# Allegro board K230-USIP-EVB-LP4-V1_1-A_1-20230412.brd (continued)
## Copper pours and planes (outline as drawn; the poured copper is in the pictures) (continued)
GND on TOP: 64.64,40.01 64.52,40.13 64.52,42.8 64.01,43.31 60.96,43.31 60.83,43.43 60.83,47.75 60.96,47.88 63.37,47.88 63.5,48.01 63.5,50.55 63.63,50.67 66.93,50.67 67.06,50.55 67.06,43.69 67.31,43.43 75.18,43.43 75.31,43.31 75.31,40.13 75.18,40.01
GND on TOP: 59.31,85.47 59.31,88.39 59.44,88.52 62.61,88.52 62.87,88.27 62.87,85.47 62.74,85.34 59.44,85.34
GND on TOP: 67.18,9.91 67.31,9.78 67.31,2.03 67.18,1.91 45.47,1.91 45.34,2.03 45.34,9.78 45.47,9.91
GND on TOP: 23.37,64.9 23.24,64.77 20.45,64.77 20.32,64.9 20.32,66.55 20.45,66.67 23.24,66.67 23.37,66.55 ; 1 cut-out
GND on TOP: 31.62,19.68 31.5,19.81 31.5,21.59 31.62,21.72 34.67,21.72 34.8,21.59 34.8,19.81 34.67,19.68
GND on BOTTOM: 54.36,119.51 54.36,129.54 56.64,131.83 60.83,131.83 60.96,131.7 60.96,128.27 58.8,126.11 58.8,124.33 60.96,122.17 60.96,118.24 60.83,118.11 55.75,118.11
GND on BOTTOM: 1.27,127.51 7.49,127.51 14.35,134.37 38.1,134.37 38.61,133.86 38.61,122.05 37.85,121.28 28.7,121.28 27.43,120.02 27.43,103.38 27.18,103.12 1.27,103.12 1.02,103.38 1.02,127.25
GND on BOTTOM: 21.34,49.53 21.21,49.66 21.21,50.67 21.34,50.8 23.11,50.8 23.24,50.67 23.24,49.66 23.11,49.53
GND on BOTTOM: 20.07,47.12 20.07,46.1 19.94,45.97 18.92,45.97 18.8,46.1 18.8,47.12 18.92,47.24 19.94,47.24
GND on BOTTOM: 35.81,50.67 35.94,50.55 35.94,49.66 35.81,49.53 34.04,49.53 33.91,49.66 33.91,50.55 34.04,50.67
GND on BOTTOM: 41.27,116.97 41.4,116.84 41.4,116.33 41.27,116.2 40.64,116.2 40.51,116.08 40.51,115.57 40.39,115.44 36.45,115.44 36.32,115.57 36.32,116.84 36.45,116.97
GND on BOTTOM: 21.34,45.59 22.86,45.59 22.99,45.47 22.99,44.2 22.86,44.07 21.34,44.07 21.21,44.2 21.21,45.47
GND on BOTTOM: 31.62,47.24 32.64,47.24 32.77,47.12 32.77,46.1 32.64,45.97 31.62,45.97 31.5,46.1 31.5,47.12
GND on BOTTOM: 73.66,89.28 75.69,89.28 75.82,89.15 75.82,85.98 75.69,85.85 73.66,85.85 73.53,85.98 73.53,89.15
GND on BOTTOM: 2,0.64 1.03,1.03 0.64,2 0.64,14.99 0.89,15.24 66.55,15.24 66.93,14.86 66.93,1.14 66.42,0.64
GND on BOTTOM: 33.78,44.07 33.78,45.59 33.91,45.72 35.56,45.72 35.69,45.59 35.69,44.07 35.56,43.94 33.91,43.94
GND on BOTTOM: 57.54,111.53 57.67,111.65 63.76,111.65 63.89,111.53 63.89,105.43 63.76,105.3 57.67,105.3 57.54,105.43
GND on GND02, GND05, GND07: 2,0.64 1.03,1.03 0.64,2 0.64,138 1.03,138.96 2,139.36 78.07,139.36 79.03,138.96 79.43,138 79.43,2 79.03,1.03 78.07,0.64
GND on ART03: 2,0.64 1.03,1.03 0.64,2 0.64,138 1.03,138.96 2,139.36 78.07,139.36 79.03,138.96 79.43,138 79.43,2 79.03,1.03 78.07,0.64 ; 1 cut-out
GND on POWER04: 2,0.64 1.03,1.03 0.64,2 0.64,53.47 1.27,54.1 2.03,54.1 3.05,53.09 3.05,15.24 3.56,14.73 69.85,14.73 70.36,15.24 70.36,41.66 75.69,46.99 75.69,116.2 57.53,134.37 5.59,134.37 4.06,132.84 4.06,115.99 2.01,114 4.06,112.01 4.06,78.3 3.53,77.49 4.04,76.65 4.04,75.75 3.53,74.84 4.2,74.05 4.19,74.04 4.19,72.14 3.81,71.75 1.14,71.75 0.64,72.26 0.64,78.65 0.69,78.74 0.79,78.74 1.45,79.11 0.79,79.48 0.69,79.48 0.64,79.56 0.64,138 1.03,138.96 2,139.36 78.07,139.36 79.03,138.96 79.43,138 79.43,2 79.03,1.03 78.07,0.64
GND on ART06: 1.02,89.41 0.64,89.79 0.64,138 1.03,138.96 2,139.36 26.04,139.36 26.29,139.11 26.29,136.78 5.59,116.08 5.59,89.79 5.21,89.41
GND on ART06: 47.75,34.8 65.28,34.8 65.53,34.54 65.53,20.7 63.25,18.41 47.5,18.41 47.37,18.54 47.37,34.42
GND on ART06: 74.68,123.44 69.72,118.49 64.77,118.49 62.99,116.71 56.01,116.71 51.56,112.27 50.55,112.27 50.42,112.39 50.42,114.94 54.61,119.13 54.61,132.72 56.01,134.11 71.37,134.11 74.68,130.81
GND on ART06: 10.16,41.27 33.53,41.27 33.78,41.02 33.78,14.86 33.53,14.61 10.29,14.61 9.91,14.99 9.91,41.02
GND on ART06: 2,0.64 1.03,1.03 0.64,2 0.64,9.4 1.02,9.78 30.48,9.78 30.73,9.53 30.73,1.14 30.23,0.64
GND on ART06: 45.09,1.02 45.09,10.29 50.29,15.49 66.74,15.49 74.36,23.11 74.36,53.66 72.01,56.01 72.01,81.03 75.56,84.58 75.56,108.46 74.17,109.86 74.17,119.57 75.5,120.9 75.5,131.38 71.75,135.13 59.56,135.13 59.44,135.25 59.44,139.24 59.56,139.36 78.07,139.36 79.03,138.96 79.43,138 79.43,2 79.03,1.03 78.07,0.64 45.47,0.64
VBUS on TOP: 73.03,11.18 69.47,11.18 69.22,11.43 69.22,16.26 69.72,16.76 73.15,16.76 73.28,16.64 73.28,16.26 73.15,16.13 71.25,16.13 71.12,16 71.12,11.94 71.25,11.81 73.03,11.81 73.15,11.68 73.15,11.3
VBUS_IN on TOP: 67.94,16.26 67.94,11.81 67.69,11.56 47.62,11.56 47.5,11.68 47.5,19.05 47.62,19.18 54.99,19.18 55.12,19.05 55.12,18.29 55.24,18.16 63.25,18.16 65.79,20.7 65.79,32.77 65.91,32.89 71.63,32.89 71.75,33.02 71.75,34.16 71.88,34.29 73.41,34.29 73.53,34.16 73.53,30.73 72.64,29.84 70.87,29.84 70.36,29.34 70.36,18.67
VDD_0V8 on TOP: 60.2,39.88 60.33,40.01 60.33,58.04 60.2,58.17 57.28,58.17 57.15,58.04 57.15,40.01 57.28,39.88
VDD_1V1 on TOP: 49.4,25.91 49.53,25.78 49.53,22.73 49.4,22.61 42.04,22.61 41.91,22.73 41.91,25.78 42.04,25.91
VDD_1V8 on TOP: 49.66,38.86 49.53,38.73 46.86,38.73 46.74,38.86 46.74,56.39 46.86,56.52 47.5,56.52 49.66,54.36
VDD_1V8 on BOTTOM: 25.4,80.01 25.53,79.88 25.53,76.71 25.4,76.58 24.38,76.58 24.26,76.71 24.26,77.34 24.13,77.47 22.35,77.47 22.23,77.6 22.23,79.88 22.35,80.01
VDD_1V8 on BOTTOM: 30.35,82.42 29.97,82.8 29.59,82.8 29.46,82.93 29.46,85.34 28.83,85.98 28.83,86.49 28.96,86.61 30.23,86.61 30.35,86.49 30.35,83.19 30.73,82.8 30.73,82.55 30.61,82.42
VDD_1V8 on BOTTOM: 36.2,114.68 37.47,114.68 37.59,114.55 37.59,113.03 36.96,112.39 36.96,111.89 36.83,111.76 36.2,111.76 36.07,111.89 36.07,114.55
VDD_1V8 on POWER04: 3.56,16.13 3.56,53.34 1.02,55.88 1.02,70.1 2.03,71.12 5.08,71.12 5.21,71.25 5.21,132.72 5.84,133.35 57.02,133.35 74.93,115.44 74.93,48.9 69.47,43.43 69.47,16 69.25,15.78 3.91,15.78 ; 1 cut-out
VDD_1V8 on ART06: 24.96,77.41 24.96,79.57 28.45,83.06 30.86,83.06 30.99,82.93 30.99,80.01 31.11,79.88 32.77,79.88 32.89,79.76 32.89,77.72 32.77,77.6 26.04,77.6 25.65,77.22 25.15,77.22
VDD_3V3 on TOP: 69.47,110.74 72.52,110.74 72.64,110.62 72.64,109.98 72.52,109.86 69.47,109.86 69.34,109.98 69.34,110.62
VDD_3V3 on TOP: 41.53,34.67 45.59,34.67 45.72,34.54 45.72,33.27 45.59,33.15 41.53,33.15 41.4,33.27 41.4,34.54
VDD_3V3 on TOP: 34.8,14.99 34.67,14.86 31.62,14.86 31.5,14.99 31.5,19.18 31.62,19.3 34.67,19.3 34.8,19.18
VDD_3V3 on TOP: 50.8,129.16 50.93,129.03 50.93,128.4 50.8,128.27 46.61,128.27 46.48,128.4 46.48,129.03 46.61,129.16
VDD_3V3 on TOP: 63.88,22.1 64.01,21.97 64.01,19.81 62.87,18.67 60.07,18.67 59.94,18.8 59.94,21.97 60.07,22.1
VDD_3V3 on TOP: 21.59,26.29 20.95,25.65 20.95,21.59 20.83,21.46 11.68,21.46 11.56,21.59 11.56,30.35 11.68,30.48 21.46,30.48 21.59,30.35
VDD_3V3 on BOTTOM: 70.87,89.28 72.9,89.28 73.03,89.15 73.03,85.98 72.9,85.85 70.87,85.85 70.74,85.98 70.74,89.15
VDD_3V3 on BOTTOM: 34.16,80.9 34.29,80.77 35.94,80.77 36.07,80.64 36.07,80.14 35.94,80.01 33.53,80.01 33.15,80.39 33.15,80.77 33.27,80.9
VDD_3V3 on BOTTOM: 40.51,114.68 40.64,114.55 40.64,113.67 40.51,113.54 37.97,113.54 37.85,113.67 37.85,114.55 37.97,114.68
VDD_3V3 on BOTTOM: 9.14,40.13 14.22,35.05 14.22,19.68 14.1,19.56 6.99,19.56 6.86,19.68 6.86,32.13 2.92,36.07 2.92,57.53 1.02,59.44 1.02,63.37 1.27,63.63 9.02,63.63 9.14,63.5
VDD_3V3 on BOTTOM: 27.69,85.22 27.69,82.55 27.56,82.42 26.92,82.42 26.8,82.55 26.8,85.22 26.92,85.34 27.56,85.34
VDD_3V3 on ART03: 3.17,10.41 3.17,25.65 3.3,25.78 67.69,25.78 68.71,26.8 68.71,84.84 62.48,91.06 32.26,91.06 28.96,87.76 28.96,82.3 28.83,82.17 26.92,82.17 26.8,82.3 26.8,84.2 25.27,85.72 16.51,85.72 11.43,90.81 5.71,90.81 5.52,91 5.52,124.14 11.3,129.92 59.56,129.92 72.39,117.09 72.39,112.65 75.56,109.47 75.56,14.1 71.5,10.03 3.56,10.03
VDD_3V3 on ART06: 40.26,34.42 45.21,34.42 45.34,34.29 45.34,22.48 45.21,22.35 40.26,22.35 40.13,22.48 40.13,34.29
VDD_5V on TOP: 51.44,27.18 51.44,28.19 51.94,28.7 51.94,29.34 51.82,29.46 51.31,29.46 50.16,28.32 50.16,27.18 50.29,27.05 51.31,27.05
VDD_5V on TOP: 72.9,38.61 73.03,38.48 73.03,35.31 72.9,35.18 70.36,35.18 68.58,33.4 64.64,33.4 64.52,33.53 64.52,38.48 64.64,38.61
VDD_5V on TOP: 25.27,20.95 25.27,18.8 25.15,18.67 22.1,18.67 21.97,18.8 21.97,20.95 22.1,21.08 25.15,21.08
VDD_5V on TOP: 28.83,25.53 28.45,25.15 26.92,25.15 26.8,25.27 26.8,25.53 26.92,25.65 27.81,25.65 28.32,26.16 28.32,27.94 28.45,28.07 31.11,28.07 31.24,27.94 31.24,25.65 31.11,25.53
VDD_5V on TOP: 50.42,38.1 51.18,38.1 51.31,37.97 51.31,36.83 51.94,36.2 51.94,35.69 51.82,35.56 51.31,35.56 50.29,36.58 50.29,37.97
VDD_5V on TOP: 53.47,29.59 53.98,29.59 55.12,28.45 55.12,27.18 54.99,27.05 53.98,27.05 53.85,27.18 53.85,28.19 53.34,28.7 53.34,29.46
VDD_5V on TOP: 60.33,74.93 60.83,74.93 60.96,74.8 60.96,69.72 60.83,69.6 58.8,69.6 58.67,69.72 58.67,73.28
VDD_5V on TOP: 53.98,38.23 54.99,38.23 55.12,38.1 55.12,36.83 53.85,35.56 53.47,35.56 53.34,35.69 53.34,36.32 53.85,36.83 53.85,38.1
VDD_5V on TOP: 20.45,36.45 20.32,36.32 18.67,36.32 18.16,36.83 14.73,36.83 14.61,36.96 14.61,38.61 14.73,38.73 20.32,38.73 20.45,38.61
VDD_5V on BOTTOM: 15.24,17.02 14.99,17.27 14.99,37.59 15.11,37.72 24.13,37.72 24.26,37.59 24.26,27.56 24.38,27.43 49.15,27.43 49.4,27.69 49.4,44.2 49.91,44.7 58.8,44.7 58.8,73.66 58.93,73.79 61.59,73.79 61.85,73.53 61.85,43.81 66.29,39.37 66.29,20.95 62.36,17.02 ; 3 cut-outs
VDD_5V_O on TOP: 10.54,88.77 10.41,88.65 8.76,88.65 8.64,88.77 8.64,90.68 8.76,90.81 10.41,90.81 10.54,90.68
VDD_5V_O on TOP: 39.62,135.51 39.5,135.64 39.5,136.65 39.62,136.78 47.5,136.78 47.62,136.65 47.62,135.64 47.5,135.51
VDD_5V_O on TOP: 14.61,36.2 16.38,36.2 16.76,36.58 17.78,36.58 17.91,36.45 17.91,31.37 17.78,31.24 14.61,31.24 14.48,31.37 14.48,36.07
VDD_5V_O on BOTTOM: 64.64,55.24 66.93,52.96 66.93,44.45 70.87,40.51 70.87,26.92 70.74,26.8 67.06,26.8 66.93,26.92 66.93,39.5 62.36,44.07 62.36,73.66 60.58,75.44 60.58,78.36 60.71,78.49 64.52,78.49 64.64,78.36
VDD_5V_O on ART03: 2.92,90.3 3.05,90.42 10.54,90.42 10.73,90.23 10.73,85.28 8.89,83.44 8.89,39.75 14.22,34.42 67.56,34.42 67.69,34.29 67.69,26.92 67.56,26.8 10.16,26.8 2.92,34.04
VDD_5V_O on ART06: 10.92,89.92 10.92,114.05 32.38,135.51 43.31,135.51 43.43,135.64 43.43,137.41 43.31,137.54 29.34,137.54 7.24,115.44 7.24,88.77 7.37,88.65 9.65,88.65
VDD_CORE_0V8 on TOP: 45.97,65.02 45.97,67.18 46.1,67.31 49.53,67.31 51.18,65.66 51.18,65.02 51.05,64.9 46.1,64.9
VDD_CORE_0V8 on TOP: 44.32,72.01 43.94,72.39 43.18,72.39 42.93,72.64 41.27,72.64 41.15,72.77 41.15,73.28 41.27,73.41 45.34,73.41 45.47,73.28 45.47,72.14 45.34,72.01
VDD_CORE_0V8 on TOP: 41.66,80.39 41.66,78.36 41.53,78.23 40.39,78.23 40.01,78.61 40.01,80.39 40.13,80.52 41.53,80.52
VDD_CORE_0V8 on TOP: 55.88,57.91 55.88,56.01 55.75,55.88 53.85,55.88 53.72,56.01 53.72,64.39 53.85,64.52 56.52,64.52 56.64,64.39 56.64,58.67
VDD_CORE_0V8 on POWER04: 41.78,57.4 41.78,66.93 31.5,77.22 31.24,77.22 30.35,78.11 26.04,78.11 25.78,78.36 25.78,87.38 26.8,88.39 47.5,88.39 64.52,71.37 64.52,56.77 64.14,56.39 42.8,56.39
VDD_KPU_0V8 on TOP: 54.61,85.72 49.91,85.72 49.78,85.85 49.78,88.39 49.91,88.52 58.8,88.52 58.93,88.39 58.93,85.6 58.8,85.47 54.86,85.47
VDD_KPU_0V8 on TOP: 59.69,27.43 59.69,29.34 61.21,30.86 61.21,42.55 61.34,42.67 63.88,42.67 64.01,42.55 64.01,28.07 63.25,27.3 59.82,27.3
VDD_KPU_0V8 on TOP: 42.04,82.8 41.91,82.68 40.77,82.68 40.64,82.8 40.64,85.09 40.89,85.34 41.91,85.34 42.04,85.22
VDD_KPU_0V8 on TOP: 53.72,46.23 53.72,55.37 53.85,55.5 56.39,55.5 56.52,55.37 56.52,48.64 55.75,47.88 55.75,46.23 55.63,46.1 53.85,46.1
VDD_KPU_0V8 on ART03: 67.94,35.31 67.82,35.18 57.02,35.18 56.9,35.31 56.9,43.18 49.59,50.48 49.59,73.34 42.67,80.26 29.59,80.26 29.46,80.39 29.46,87.12 32.13,89.79 62.48,89.79 67.94,84.33
DDR_1V8 on TOP: 46.1,51.94 45.97,51.82 44.07,51.82 43.94,51.94 43.94,53.85 43.69,54.1 43.69,54.99 43.81,55.12 45.97,55.12 46.1,54.99
DDR_1V8 on BOTTOM: 21.59,49.02 22.99,49.02 23.11,48.9 23.11,48.13 22.99,48.01 21.59,48.01 21.46,48.13 21.46,48.9
DDR_1V8 on BOTTOM: 34.29,49.02 35.81,49.02 35.94,48.9 35.94,48.13 35.81,48.01 34.29,48.01 34.16,48.13 34.16,48.9
DDR_1V8 on BOTTOM: 34.29,56.01 35.18,55.12 36.58,55.12 36.83,54.86 36.83,53.72 36.7,53.59 34.92,53.59 34.8,53.72 33.27,53.72 33.15,53.85 33.15,54.48 32.77,54.86 30.73,54.86 30.23,54.36 29.59,54.36 29.34,54.1 29.34,48.64 29.21,48.51 27.94,48.51 27.81,48.64 27.81,53.98 27.69,54.1 27.05,54.1 26.92,54.23 26.92,54.86 26.8,54.99 25.27,54.99 25.15,54.86 25.15,53.09 25.02,52.96 19.56,52.96 19.3,53.21 19.3,54.86 19.43,54.99 19.94,54.99 20.07,54.86 20.07,54.36 20.19,54.23 23.24,54.23 23.37,54.36 23.37,55.88 23.5,56.01
DDR_1V8 on ART06: 41.02,43.81 46.1,48.9 46.1,54.99 45.97,55.12 38.48,55.12 38.35,54.99 38.35,51.94 37.21,50.8 18.8,50.8 18.67,50.93 18.67,54.99 18.54,55.12 14.22,55.12 14.1,54.99 14.1,43.94 14.22,43.81
DDR_CORE_0V8 on TOP: 60.96,56.13 60.83,56.26 60.83,61.09 57.02,64.9 52.58,64.9 49.4,68.07 46.61,68.07 46.48,68.2 46.48,70.74 46.61,70.87 49.66,70.87 53.85,66.67 58.17,66.67 62.74,62.1 62.74,56.26 62.61,56.13
DDR_CORE_0V8 on ART03: 28.83,77.6 28.19,76.96 24.13,76.96 23.18,76.01 23.11,76.07 20.83,76.07 20.7,76.2 20.7,76.96 22.86,79.12 25.15,79.12 25.78,79.76 41.27,79.76 48.64,72.39 48.64,68.2 48.51,68.07 44.07,68.07 34.54,77.6
DDR_VAA_1V8 on TOP: 44.07,48.01 43.94,48.13 43.94,50.16 43.81,50.29 43.81,51.18 43.94,51.31 46.1,51.31 46.23,51.18 46.23,48.13 46.1,48.01
DDR_VAA_1V8 on ART03: 33.4,73.41 33.4,74.3 32,75.69 30.35,75.69 29.72,76.33 28.96,76.33 28.83,76.45 28.83,77.09 28.96,77.22 33.91,77.22 48.01,63.12 48.01,48.39 47.88,48.26 43.31,48.26 43.18,48.39 43.18,63.63
DDR_VDDQ_1V1 on TOP: 23.24,67.18 20.45,67.18 20.32,67.31 20.32,68.96 20.45,69.09 23.24,69.09 23.37,68.96 23.37,67.31 ; 1 cut-out
DDR_VDDQ_1V1 on TOP: 43.69,26.54 43.56,26.42 34.54,26.42 33.78,27.18 33.78,42.93 33.91,43.05 38.35,43.05 38.48,42.93 38.48,29.84 38.73,29.59 43.43,29.59 43.69,29.34
DDR_VDDQ_1V1 on BOTTOM: 23.11,47.75 23.24,47.62 23.24,46.35 23.11,46.23 20.95,46.23 20.83,46.35 20.83,47.62 20.95,47.75
DDR_VDDQ_1V1 on BOTTOM: 35.81,47.75 35.94,47.62 35.94,46.35 35.81,46.23 33.66,46.23 33.53,46.35 33.53,47.62 33.66,47.75
DDR_VDDQ_1V1 on POWER04: 30.1,77.72 40.89,66.93 40.89,40.77 40.77,40.64 17.02,40.64 16.89,40.77 16.89,70.99 22.48,76.58 25.53,76.58 26.67,77.72
DDR_VREF on BOTTOM: 28.45,75.69 29.72,75.69 29.84,75.56 29.84,73.91 29.21,73.28 29.21,69.47 29.08,69.34 28.45,69.34 28.32,69.47 28.32,73.41 28.83,73.91 28.83,74.8 28.32,75.31 28.32,75.56
FTVCC_1V8 on BOTTOM: 65.02,101.6 65.02,102.87 64.9,103 61.34,103 61.09,102.74 57.4,102.74 57.02,103.12 56.13,103.12 56.01,103 56.01,101.6 56.52,101.09 59.31,101.09 59.69,101.47 64.9,101.47
FTVCC_3V3 on TOP: 69.34,113.28 71.25,113.28 71.37,113.16 71.37,111.63 71.25,111.51 69.34,111.51 69.22,111.63 69.22,113.16
FTVCC_3V3 on TOP: 65.02,97.03 64.9,96.9 62.74,96.9 62.61,97.03 62.61,98.42 62.74,98.55 64.9,98.55 65.02,98.42
FTVCC_3V3 on ART06: 57.02,102.36 58.67,102.36 63.63,97.41 71.37,97.41 71.88,97.92 71.88,112.78 70.04,114.62 56.83,114.62 53.34,111.12 53.34,106.05
MIPI_0V8 on TOP: 56.64,40.89 56.52,40.77 54.23,40.77 54.1,40.89 54.1,45.47 54.23,45.59 56.52,45.59 56.64,45.47
MIPI_0V8 on ART03: 19.05,81.79 12.83,75.56 12.83,43.56 16.76,39.62 46.35,39.62 49.91,43.18 55.75,43.18 56.13,42.8 56.13,35.69 55.75,35.31 14.99,35.31 9.4,40.89 9.4,78.74 15.75,85.09 25.4,85.09 26.16,84.33 26.16,81.92 26.04,81.79
MIPI_1V8 on TOP: 46.1,38.73 45.97,38.61 44.07,38.61 43.94,38.73 43.94,43.69 44.07,43.81 45.97,43.81 46.1,43.69
MIPI_1V8 on ART03: 25.78,80.26 25.02,79.5 22.73,79.5 16.38,73.15 16.38,45.97 18.8,43.56 46.1,43.56 46.23,43.43 46.23,40.39 45.97,40.13 17.65,40.13 13.59,44.2 13.59,74.3 20.83,81.53 25.65,81.53 25.78,81.41
RTC_1V8 on TOP: 44.07,55.63 43.94,55.75 43.94,58.67 44.07,58.8 47.75,58.8 47.88,58.67 47.88,57.02 47.75,56.9 46.35,56.9 46.23,56.77 46.23,55.75 46.1,55.63
RTC_1V8 on BOTTOM: 44.07,70.23 39.5,74.8 35.69,74.8 35.43,75.06 33.53,75.06 32.51,76.07 32.51,76.58 32.26,76.83 31.62,76.83 31.5,76.96 31.5,77.6 31.62,77.72 32.38,77.72 32.89,77.22 34.54,77.22 35.43,76.33 42.04,76.33 47.88,70.48 47.88,56.77 47.75,56.64 44.2,56.64 44.07,56.77
U_3V3 on TOP: 59.56,93.09 60.58,92.08 60.58,91.82 60.45,91.69 57.91,91.69 57.78,91.82 57.78,95.38 57.91,95.5 62.23,95.5 62.87,96.14 64.01,96.14 64.14,96.01 64.14,94.87 64.01,94.74 59.82,94.74 59.56,94.49
U_5V on TOP: 62.23,89.66 62.1,89.79 62.1,90.55 62.23,90.68 62.87,90.68 62.99,90.81 62.99,91.44 62.87,91.57 62.23,91.57 62.1,91.69 62.1,92.2 62.99,93.09 62.99,94.23 63.12,94.36 64.14,94.36 64.64,93.85 68.2,93.85 70.48,96.14 70.48,101.98 70.61,102.11 73.28,102.11 74.68,103.5 74.68,104.9 73.28,106.3 71.75,106.3 71.63,106.43 71.63,106.81 71.75,106.93 73.66,106.93 75.31,105.28 75.31,103.38 73.41,101.47 71.37,101.47 71.25,101.35 71.25,95.25 67.82,91.82 64.26,91.82 64.14,91.69 64.14,89.79 64.01,89.66
USB0_OTG_VBUS on TOP: 71.88,76.07 73.79,76.07 75.31,74.55 75.31,72.14 73.66,70.48 70.87,70.48 70.74,70.61 70.74,70.99 70.87,71.12 73.28,71.12 74.68,72.52 74.68,74.17 73.41,75.44 71.88,75.44 71.75,75.56 71.75,75.95
USB1_OTG_VBUS on TOP: 73.15,64.01 73.28,63.88 73.28,63.5 73.15,63.37 71.63,63.37 71.5,63.25 70.74,63.25 70.61,63.37 70.61,63.88 70.74,64.01
USB1_OTG_VBUS on TOP: 73.15,59.18 73.28,59.05 73.28,58.55 73.15,58.42 70.87,58.42 70.74,58.55 70.74,59.05 70.87,59.18
N21034668 on BOTTOM: 35.94,82.42 36.07,82.3 36.07,81.41 35.94,81.28 33.02,81.28 32.89,81.15 32.38,81.15 32.26,81.28 32.26,81.53 32.64,81.92 32.64,82.3 32.77,82.42
N21842448 on TOP: 58.04,84.84 57.91,84.71 57.91,81.92 58.04,81.79 62.74,81.79 62.87,81.92 62.87,84.71 62.74,84.84
N21842648 on TOP: 59.05,79.88 59.05,80.52 59.18,80.64 61.72,80.64 61.85,80.52 61.85,78.49 61.72,78.36 60.58,78.36
N21859857 on TOP: 24.89,26.67 25.27,26.29 25.27,25.4 25.15,25.27 22.48,25.27 22.35,25.4 22.35,27.94 22.48,28.07 24.77,28.07 24.89,27.94
N21888350 on TOP: 53.98,34.04 53.85,34.16 53.85,34.92 56.64,37.72 59.44,37.72 59.56,37.59 59.56,34.16 59.44,34.04
N21888844 on TOP: 46.99,37.47 49.66,37.47 49.78,37.34 49.78,36.45 51.18,35.05 51.44,35.05 51.56,34.92 51.56,34.16 51.44,34.04 50.55,34.04 48.39,36.2 46.99,36.2 46.86,36.32 46.86,37.34
N21889896 on TOP: 55.63,25.91 61.85,25.91 61.98,25.78 61.98,22.73 61.85,22.61 55.63,22.61 55.5,22.73 55.5,25.78
N21890180 on TOP: 53.85,29.97 53.85,30.61 53.98,30.73 54.99,30.73 56.52,29.21 57.91,29.21 58.04,29.08 58.04,27.43 57.91,27.3 55.63,27.3 55.5,27.43 55.5,28.32
N21891752 on TOP: 46.86,27.56 46.86,28.83 46.99,28.96 48.51,28.96 50.29,30.73 51.44,30.73 51.56,30.61 51.56,29.97 51.44,29.84 51.18,29.84 49.78,28.45 49.78,27.69 49.53,27.43 46.99,27.43
N21913184 on TOP: 30.73,20.83 30.73,17.78 30.61,17.65 28.7,17.65 28.57,17.78 28.57,18.8 28.45,18.92 26.67,18.92 26.54,19.05 26.54,20.83 26.67,20.95 30.61,20.95

Small or netless copper shapes (teardrops, artwork), in the pictures only: 23 on TOP

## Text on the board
Ref Des/Silkscreen Bottom: CA_A0 | CA_A1 | USB0_OTG_EN | USB1_OTG_EN | GND | VDD_1V8 | VDD_3V3 | GPIO26 | GPIO28 | GPIO30 | GPIO33 | GPIO34 | GPIO35 | GPIO36 | GPIO37 | CS_A | CKE_A | GPIO27 | GPIO29 | GPIO32 | GPIO31 | GPIO52 | GPIO53 | UART3_RXD | UART3_TXD | VDD_5V_O | A9 | DQ_A8 | DQ_A9 | DQ_B0 | DQ_B1 | B0 | B8 | B1 | DQ_B8 | DQ_B9 | DQS0_T_B | DQS0_C_B | CS_B | CKE_B | DQS0_C_A | DQS0_T_A | CK_T_A | CK_C_A | DQS1_T_A | DQS1_C_A | DQ_A0 | DQ_A1 | A0 | A1 | A8 | RESET | CA_B1 | CA_B0 | CK_T_B | CK_C_B | SYS_SW | PW_EN | DQS1_T_B | OUT0 | DQS1_C_B | INT5 | INT4 | RTC_1V8 | INT3 | INT2 | INT1 | INT0 | SYS_ON_OFF | K230-USIP-EVB-LP4-V1.1-A.1 | 2023-04-12
Ref Des/Silkscreen Top: 5V | TX1_D3P | GND | TX1_D2N | 3V3 | VDDQ_1V1 | MIPI_1V8 | AVDD_1V8 | VAA_1V8 | RTC_1V8 | DDR_1V8 | ADC0--5 | SPL | SPR | HPOL | HPOR | HPL | HPR | KPU_0V8 | PLL_0V8 | MIPI_0V8 | H | L | UART0/3 | SDR | SDL | MUTE | USB0 | USB1 | 1V8 | TCK | TDO | TDI | TMS | RST | NC | RX1_D3P | RX1_CLKP | TX0_D1P | RX1_D2N | TX0_D0N | RX0_D0P | RX0_CLKN | TX0_CLKP | RX0_D1P | RX2_D5N | G0 | CORE_0V8 | DDR_CORE_0V8 | RESET | RX2_D4P | RX2_CLKN | 2023-04-12 | K230-USIP-EVB-LP4-V1.1-A.1 | DC 5V | : | OFF | ON
User.23: FIGURE | SIZE | 8.0 | 10.0 | 40.0 | 45.0 | 55.0 | 125.0 | 24.0 | 28.0 | 48.0 | 50.0x30.0 | 70.0x30.0 | 70.0x40.0 | DRILL CHART: TOP to BOTTOM | ALL UNITS ARE IN MILS | PLATED | NON-PLATED | QTY | 712 | 949 | 81 | 2 | 6 | 8
